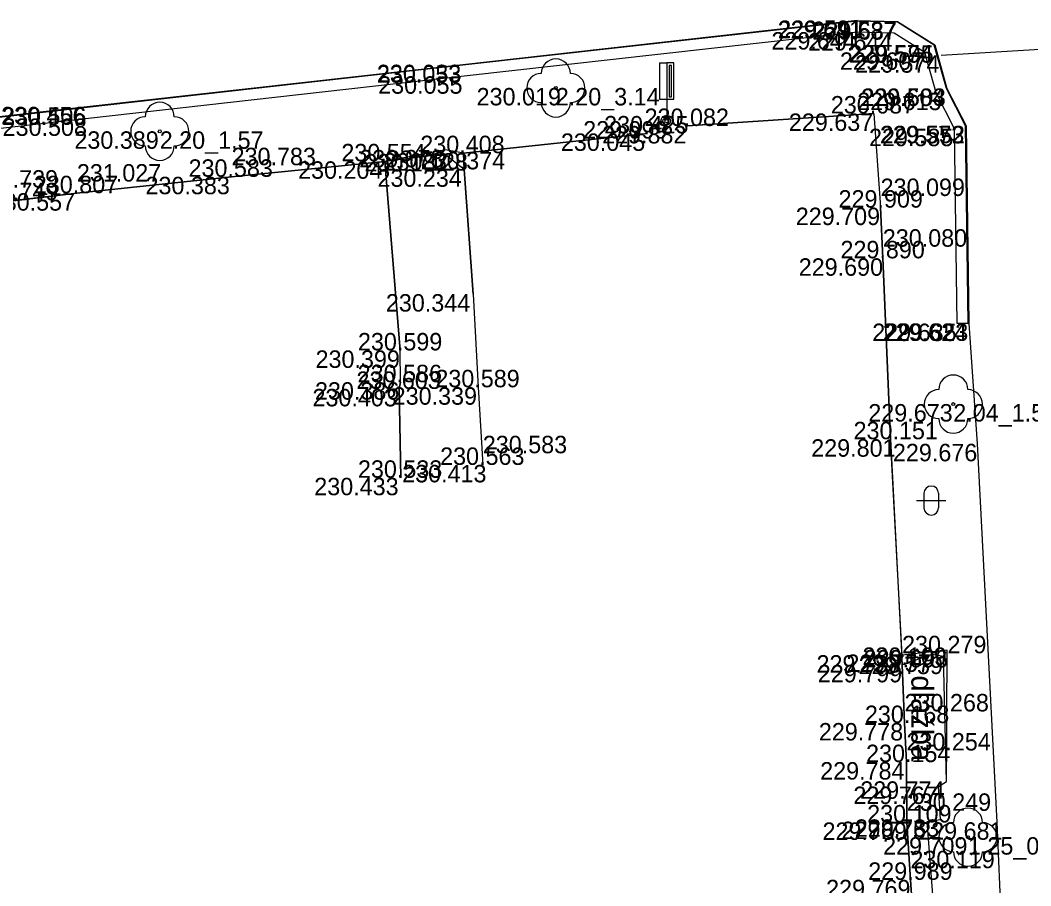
# Model space of a CAD drawing. Extents: x -599516 to -599132, y -1163668 to -1163119.
# Drawn here: x -599435.97 to -599418.59, y -1163529.55 to -1163514.66 of the extents above; entities that cross this region are included whole.
import ezdxf

# ---------------------------------------------------------------- set-up
doc = ezdxf.new("R2010")
doc.units = 0
for name, color, linetype in [('Bod-oznac1', 7, 'Continuous'), ('Bod-oznac2', 7, 'Continuous'), ('Bod-oznac3', 7, 'Continuous'), ('Bod-vyska1', 7, 'Continuous'), ('Bod-vyska2', 7, 'Continuous'), ('Bod-vyska3', 7, 'Continuous'), ('Z_cela-hrobu-dolni-linie', 7, 'Continuous'), ('Z_cela-hrobu-horni-linie', 7, 'Continuous'), ('Z_chodnik', 7, 'Continuous'), ('Z_komunikace', 7, 'Continuous'), ('Z_kultury-znacky', 7, 'Continuous'), ('Z_obvod-kmene-spodek-ve-vysce1_2m', 7, 'Continuous'), ('Z_popis-budov-povrchu', 7, 'Continuous'), ('Z_povrchy-rozhrani-typu', 7, 'Continuous'), ('Z_stromy-kere', 7, 'Continuous'), ('Z_terenni-hrana', 7, 'Continuous'), ('Z_znacky-ostatni-orientacni-sloupek', 7, 'Continuous'), ('Z_zpevnene-plochy', 7, 'Continuous')]:
    doc.layers.add(name, color=color, linetype=linetype)

msp = doc.modelspace()

# ---------------------------------------------------------------- linework, layer by layer
at = {"layer": 'Bod-oznac1'}
for p, q in [((-599421.581, -1163514.662), (-599421.581, -1163514.662)), ((-599421.581, -1163514.672), (-599421.581, -1163514.672)), ((-599420.887, -1163514.692), (-599420.887, -1163514.692)), ((-599420.884, -1163514.682), (-599420.884, -1163514.682)), ((-599421.573, -1163514.862), (-599421.573, -1163514.862)), ((-599420.944, -1163514.88), (-599420.944, -1163514.88)), ((-599420.256, -1163515.089), (-599420.256, -1163515.089)), ((-599420.247, -1163515.083), (-599420.247, -1163515.083)), ((-599420.418, -1163515.211), (-599420.418, -1163515.211)), ((-599420.133, -1163515.26), (-599420.133, -1163515.26)), ((-599428.36, -1163515.423), (-599428.36, -1163515.423)), ((-599428.359, -1163515.433), (-599428.359, -1163515.433)), ((-599428.338, -1163515.622), (-599428.338, -1163515.622)), ((-599426.762, -1163515.823), (-599426.762, -1163515.823)), ((-599420.223, -1163515.904), (-599420.223, -1163515.904)), ((-599420.045, -1163515.835), (-599420.045, -1163515.835)), ((-599420.036, -1163515.831), (-599420.036, -1163515.831)), ((-599434.819, -1163516.148), (-599434.819, -1163516.148)), ((-599434.818, -1163516.158), (-599434.818, -1163516.158)), ((-599421.293, -1163516.262), (-599421.293, -1163516.262)), ((-599434.796, -1163516.347), (-599434.796, -1163516.347)), ((-599424.855, -1163516.393), (-599424.855, -1163516.393)), ((-599424.496, -1163516.477), (-599424.496, -1163516.477)), ((-599419.717, -1163516.476), (-599419.717, -1163516.476)), ((-599419.707, -1163516.474), (-599419.707, -1163516.474)), ((-599433.572, -1163516.569), (-599433.572, -1163516.569)), ((-599425.186, -1163516.605), (-599425.186, -1163516.605)), ((-599419.906, -1163516.524), (-599419.906, -1163516.524)), ((-599428.675, -1163516.959), (-599428.675, -1163516.959)), ((-599428.661, -1163516.888), (-599428.661, -1163516.888)), ((-599428.348, -1163516.944), (-599428.348, -1163516.944)), ((-599429.704, -1163517.085), (-599429.704, -1163517.085)), ((-599432.337, -1163517.351), (-599432.337, -1163517.351)), ((-599428.337, -1163517.223), (-599428.337, -1163517.223)), ((-599434.997, -1163517.633), (-599434.997, -1163517.633)), ((-599421.177, -1163517.881), (-599421.177, -1163517.881)), ((-599421.139, -1163518.753), (-599421.139, -1163518.753)), ((-599428.182, -1163519.369), (-599428.182, -1163519.369)), ((-599419.861, -1163519.876), (-599419.861, -1163519.876)), ((-599419.671, -1163519.873), (-599419.671, -1163519.873)), ((-599419.661, -1163519.873), (-599419.661, -1163519.873)), ((-599429.436, -1163520.337), (-599429.436, -1163520.337)), ((-599429.457, -1163520.999), (-599429.457, -1163520.999)), ((-599429.435, -1163520.884), (-599429.435, -1163520.884)), ((-599428.099, -1163520.971), (-599428.099, -1163520.971)), ((-599419.927, -1163521.26), (-599419.927, -1163521.26)), ((-599421.006, -1163521.865), (-599421.006, -1163521.865)), ((-599419.516, -1163521.944), (-599419.516, -1163521.944)), ((-599428.017, -1163522.306), (-599428.017, -1163522.306)), ((-599429.424, -1163522.528), (-599429.424, -1163522.528)), ((-599420.032, -1163525.49), (-599420.032, -1163525.49)), ((-599420.807, -1163525.579), (-599420.807, -1163525.579)), ((-599420.29, -1163525.567), (-599420.29, -1163525.567)), ((-599420.094, -1163525.604), (-599420.094, -1163525.604)), ((-599420.808, -1163525.746), (-599420.808, -1163525.746)), ((-599420.765, -1163526.746), (-599420.765, -1163526.746)), ((-599420.733, -1163527.418), (-599420.733, -1163527.418)), ((-599420.042, -1163527.749), (-599420.042, -1163527.749)), ((-599420.182, -1163527.839), (-599420.182, -1163527.839)), ((-599420.727, -1163528.456), (-599420.727, -1163528.456)), ((-599420.376, -1163528.442), (-599420.376, -1163528.442)), ((-599420.147, -1163528.403), (-599420.147, -1163528.403)), ((-599419.176, -1163528.453), (-599419.176, -1163528.453)), ((-599419.675, -1163528.709), (-599419.675, -1163528.709)), ((-599420.665, -1163529.443), (-599420.665, -1163529.443))]:
    msp.add_line(p, q, dxfattribs=at)
at = {"layer": 'Bod-oznac2'}
for p, q in [((-599421.293, -1163516.262), (-599421.293, -1163516.262)), ((-599424.496, -1163516.477), (-599424.496, -1163516.477)), ((-599425.186, -1163516.605), (-599425.186, -1163516.605)), ((-599428.348, -1163516.944), (-599428.348, -1163516.944)), ((-599429.704, -1163517.085), (-599429.704, -1163517.085)), ((-599432.337, -1163517.351), (-599432.337, -1163517.351)), ((-599428.337, -1163517.223), (-599428.337, -1163517.223)), ((-599434.997, -1163517.633), (-599434.997, -1163517.633)), ((-599421.177, -1163517.881), (-599421.177, -1163517.881)), ((-599421.139, -1163518.753), (-599421.139, -1163518.753)), ((-599429.436, -1163520.337), (-599429.436, -1163520.337)), ((-599429.457, -1163520.999), (-599429.457, -1163520.999)), ((-599429.435, -1163520.884), (-599429.435, -1163520.884)), ((-599428.099, -1163520.971), (-599428.099, -1163520.971)), ((-599421.006, -1163521.865), (-599421.006, -1163521.865)), ((-599428.017, -1163522.306), (-599428.017, -1163522.306)), ((-599429.424, -1163522.528), (-599429.424, -1163522.528)), ((-599420.808, -1163525.746), (-599420.808, -1163525.746)), ((-599420.765, -1163526.746), (-599420.765, -1163526.746)), ((-599420.733, -1163527.418), (-599420.733, -1163527.418)), ((-599420.727, -1163528.456), (-599420.727, -1163528.456)), ((-599420.665, -1163529.443), (-599420.665, -1163529.443))]:
    msp.add_line(p, q, dxfattribs=at)
at = {"layer": 'Bod-oznac3'}
for p, q in [((-599432.337, -1163517.351), (-599432.337, -1163517.351)), ((-599434.997, -1163517.633), (-599434.997, -1163517.633)), ((-599421.177, -1163517.881), (-599421.177, -1163517.881)), ((-599421.139, -1163518.753), (-599421.139, -1163518.753)), ((-599428.017, -1163522.306), (-599428.017, -1163522.306)), ((-599420.808, -1163525.746), (-599420.808, -1163525.746)), ((-599420.765, -1163526.746), (-599420.765, -1163526.746)), ((-599420.733, -1163527.418), (-599420.733, -1163527.418)), ((-599420.727, -1163528.456), (-599420.727, -1163528.456)), ((-599420.665, -1163529.443), (-599420.665, -1163529.443))]:
    msp.add_line(p, q, dxfattribs=at)
at = {"layer": 'Z_cela-hrobu-dolni-linie'}
msp.add_line((-599421.293, -1163516.262), (-599421.177, -1163517.881), dxfattribs=at)
for points in [[(-599421.293, -1163516.262), (-599424.496, -1163516.477)], [(-599425.186, -1163516.605), (-599428.348, -1163516.944), (-599428.337, -1163517.223)], [(-599429.704, -1163517.085), (-599432.337, -1163517.351), (-599434.997, -1163517.633), (-599436.025, -1163517.754), (-599436.651, -1163517.829), (-599437.614, -1163517.946), (-599438.73, -1163518.122), (-599439.095, -1163518.16), (-599440.238, -1163518.293), (-599441.648, -1163518.432), (-599442.872, -1163518.558), (-599444.321, -1163518.689), (-599445.506, -1163518.817), (-599445.475, -1163519.079), (-599446.807, -1163519.152), (-599446.846, -1163518.718), (-599447.622, -1163518.817), (-599447.636, -1163518.922), (-599449.534, -1163519.065)], [(-599420.439, -1163532.361), (-599420.588, -1163531.085), (-599420.617, -1163530.118), (-599420.665, -1163529.443), (-599420.727, -1163528.456), (-599420.733, -1163527.418), (-599420.765, -1163526.746), (-599420.808, -1163525.746), (-599420.807, -1163525.579), (-599421.006, -1163521.865), (-599421.139, -1163518.753), (-599421.177, -1163517.881)]]:
    msp.add_lwpolyline(points, dxfattribs=at)
at = {"layer": 'Z_cela-hrobu-horni-linie'}
for points in [[(-599424.496, -1163516.477), (-599421.293, -1163516.262), (-599421.177, -1163517.881), (-599421.177, -1163517.881), (-599421.139, -1163518.753), (-599421.139, -1163518.753), (-599421.006, -1163521.865), (-599420.808, -1163525.746), (-599420.808, -1163525.746), (-599420.765, -1163526.746), (-599420.765, -1163526.746), (-599420.733, -1163527.418), (-599420.733, -1163527.418), (-599420.727, -1163528.456), (-599420.727, -1163528.456), (-599420.665, -1163529.443), (-599420.665, -1163529.443), (-599420.617, -1163530.118)], [(-599428.182, -1163519.369), (-599428.337, -1163517.223), (-599428.348, -1163516.944), (-599425.186, -1163516.605)], [(-599437.614, -1163517.946), (-599434.997, -1163517.633), (-599434.997, -1163517.633), (-599432.337, -1163517.351), (-599432.337, -1163517.351), (-599429.704, -1163517.085), (-599429.436, -1163520.337)], [(-599429.435, -1163520.884), (-599429.457, -1163520.999), (-599429.424, -1163522.528)], [(-599428.099, -1163520.971), (-599428.017, -1163522.306), (-599428.017, -1163522.306)]]:
    msp.add_lwpolyline(points, dxfattribs=at)
at = {"layer": 'Z_chodnik'}
for points in [[(-599428.337, -1163517.223), (-599428.675, -1163516.959), (-599429.704, -1163517.085)], [(-599429.424, -1163522.528), (-599429.457, -1163520.999), (-599429.435, -1163520.884), (-599429.436, -1163520.337), (-599429.704, -1163517.085)], [(-599428.337, -1163517.223), (-599428.182, -1163519.369), (-599428.099, -1163520.971), (-599428.017, -1163522.306)]]:
    msp.add_lwpolyline(points, dxfattribs=at)
at = {"layer": 'Z_komunikace'}
msp.add_line((-599421.581, -1163514.662), (-599420.884, -1163514.682), dxfattribs=at)
for points in [[(-599421.581, -1163514.662), (-599428.36, -1163515.423), (-599434.819, -1163516.148), (-599441.683, -1163516.929), (-599449.913, -1163517.876), (-599458.749, -1163518.857), (-599467.027, -1163519.79), (-599473.501, -1163520.532), (-599473.927, -1163520.461), (-599474.378, -1163520.597), (-599474.641, -1163520.812), (-599479.573, -1163521.271)], [(-599420.884, -1163514.682), (-599420.247, -1163515.083), (-599420.036, -1163515.831), (-599419.707, -1163516.474), (-599419.661, -1163519.873), (-599419.516, -1163521.944), (-599419.176, -1163528.453), (-599418.955, -1163533.678), (-599418.894, -1163534.146)]]:
    msp.add_lwpolyline(points, dxfattribs=at)
at = {"layer": 'Z_kultury-znacky'}
for p, q in [((-599420.432, -1163522.795), (-599420.432, -1163523.045)), ((-599420.182, -1163522.795), (-599420.182, -1163523.045)), ((-599420.557, -1163522.92), (-599420.057, -1163522.92))]:
    msp.add_line(p, q, dxfattribs=at)
for centre, start, end in [((-599420.307, -1163522.795), 0, 180), ((-599420.307, -1163523.045), 180, 0)]:
    msp.add_arc(centre, 0.125, start, end, dxfattribs=at)
at = {"layer": 'Z_povrchy-rozhrani-typu'}
msp.add_lwpolyline([(-599420.133, -1163515.26), (-599415.884, -1163514.999)], dxfattribs=at)
at = {"layer": 'Z_stromy-kere'}
for centre in [(-599426.762, -1163515.823), (-599433.572, -1163516.569), (-599419.927, -1163521.26), (-599419.675, -1163528.709)]:
    msp.add_circle(centre, 0.025, dxfattribs=at)
for centre, start, end in [((-599426.762, -1163515.573), 0, 180), ((-599427.012, -1163515.823), 90, 270), ((-599426.512, -1163515.823), 270, 90), ((-599433.572, -1163516.319), 0, 180), ((-599426.762, -1163516.073), 180, 0), ((-599433.822, -1163516.569), 90, 270), ((-599433.322, -1163516.569), 270, 90), ((-599433.572, -1163516.819), 180, 0), ((-599419.927, -1163521.01), 0, 180), ((-599420.177, -1163521.26), 90, 270), ((-599419.677, -1163521.26), 270, 90), ((-599419.927, -1163521.51), 180, 0), ((-599419.675, -1163528.459), 0, 180), ((-599419.925, -1163528.709), 90, 270), ((-599419.425, -1163528.709), 270, 90), ((-599419.675, -1163528.959), 180, 0)]:
    msp.add_arc(centre, 0.25, start, end, dxfattribs=at)
at = {"layer": 'Z_terenni-hrana'}
for points in [[(-599428.348, -1163516.944), (-599428.661, -1163516.888), (-599429.704, -1163517.085)], [(-599420.042, -1163527.749), (-599420.032, -1163525.49), (-599420.807, -1163525.579)]]:
    msp.add_lwpolyline(points, dxfattribs=at)
at = {"layer": 'Z_znacky-ostatni-orientacni-sloupek'}
for p, q in [((-599424.98, -1163515.393), (-599424.98, -1163516.018)), ((-599424.98, -1163515.393), (-599424.855, -1163515.393)), ((-599424.98, -1163516.018), (-599424.855, -1163516.018)), ((-599424.855, -1163516.018), (-599424.855, -1163516.293))]:
    msp.add_line(p, q, dxfattribs=at)
for points in [[(-599424.855, -1163516.018), (-599424.73, -1163516.018), (-599424.73, -1163515.393), (-599424.855, -1163515.393)], [(-599424.812, -1163515.975), (-599424.772, -1163515.975), (-599424.772, -1163515.436), (-599424.812, -1163515.436)]]:
    msp.add_lwpolyline(points, close=True, dxfattribs=at)
for radius in [0.1, 0.065, 0.03]:
    msp.add_circle((-599424.855, -1163516.393), radius, dxfattribs=at)
at = {"layer": 'Z_zpevnene-plochy'}
for points in [[(-599419.671, -1163519.873), (-599419.717, -1163516.476), (-599420.045, -1163515.835), (-599420.256, -1163515.089), (-599420.887, -1163514.692), (-599421.581, -1163514.672), (-599428.359, -1163515.433), (-599434.818, -1163516.158), (-599441.682, -1163516.939), (-599449.912, -1163517.886), (-599458.748, -1163518.867), (-599467.026, -1163519.8), (-599473.501, -1163520.542), (-599473.926, -1163520.471), (-599474.373, -1163520.606), (-599474.637, -1163520.822), (-599479.572, -1163521.281), (-599480.282, -1163521.415), (-599480.802, -1163521.956), (-599481.292, -1163522.751)], [(-599419.671, -1163519.873), (-599419.861, -1163519.876), (-599419.906, -1163516.524), (-599420.223, -1163515.904), (-599420.418, -1163515.211), (-599420.944, -1163514.88), (-599421.573, -1163514.862), (-599428.338, -1163515.622), (-599434.796, -1163516.347), (-599441.66, -1163517.128), (-599449.89, -1163518.075), (-599458.727, -1163519.056), (-599467.004, -1163519.989), (-599473.506, -1163520.734), (-599473.914, -1163520.666), (-599474.282, -1163520.777), (-599474.562, -1163521.005), (-599479.545, -1163521.469), (-599480.187, -1163521.591), (-599480.651, -1163522.073), (-599481.13, -1163522.851), (-599481.292, -1163522.751)], [(-599420.588, -1163531.085), (-599420.178, -1163531.034), (-599420.376, -1163528.442), (-599420.147, -1163528.403), (-599420.182, -1163527.839), (-599420.042, -1163527.749), (-599420.094, -1163525.604), (-599420.29, -1163525.567), (-599420.808, -1163525.746)]]:
    msp.add_lwpolyline(points, dxfattribs=at)

# ---------------------------------------------------------------- texts
at = {"layer": 'Bod-vyska1'}
for s, p in [('229.641', (-599422.947, -1163514.972)), ('229.591', (-599422.936, -1163514.962)), ('229.587', (-599422.356, -1163514.982)), ('229.637', (-599422.348, -1163514.992)), ('229.644', (-599423.054, -1163515.162)), ('229.644', (-599422.425, -1163515.18)), ('229.574', (-599421.73, -1163515.383)), ('229.595', (-599421.715, -1163515.389)), ('229.607', (-599421.877, -1163515.511)), ('229.574', (-599421.616, -1163515.56)), ('230.033', (-599429.838, -1163515.723)), ('230.053', (-599429.837, -1163515.733)), ('230.055', (-599429.816, -1163515.922)), ('230.019', (-599428.124, -1163516.123)), ('229.615', (-599421.578, -1163516.204)), ('229.604', (-599421.513, -1163516.135)), ('229.583', (-599421.506, -1163516.131)), ('230.456', (-599436.299, -1163516.448)), ('230.506', (-599436.284, -1163516.458)), ('229.637', (-599422.754, -1163516.562)), ('230.508', (-599436.274, -1163516.647)), ('229.999', (-599426.291, -1163516.693)), ('229.882', (-599425.966, -1163516.777)), ('229.573', (-599421.189, -1163516.776)), ('229.552', (-599421.177, -1163516.774)), ('230.389', (-599435.04, -1163516.869)), ('230.045', (-599426.675, -1163516.905)), ('229.585', (-599421.376, -1163516.824)), ('230.078', (-599430.141, -1163517.188)), ('230.187', (-599430.053, -1163517.259)), ('230.128', (-599429.724, -1163517.244)), ('230.204', (-599431.193, -1163517.385)), ('230.383', (-599433.817, -1163517.651)), ('230.234', (-599429.828, -1163517.523)), ('230.557', (-599436.478, -1163517.933)), ('229.709', (-599422.636, -1163518.181)), ('229.690', (-599422.585, -1163519.053)), ('230.344', (-599429.684, -1163519.669)), ('229.635', (-599421.32, -1163520.176)), ('229.624', (-599421.141, -1163520.173)), ('229.623', (-599421.12, -1163520.173)), ('230.399', (-599430.893, -1163520.637)), ('230.403', (-599430.946, -1163521.299)), ('230.386', (-599430.903, -1163521.184)), ('230.339', (-599429.567, -1163521.271)), ('229.673', (-599421.388, -1163521.56)), ('229.801', (-599422.37, -1163522.165)), ('229.676', (-599420.965, -1163522.244)), ('230.413', (-599429.404, -1163522.606)), ('230.433', (-599430.915, -1163522.828)), ('229.696', (-599421.468, -1163525.79)), ('229.738', (-599422.279, -1163525.879)), ('229.757', (-599421.764, -1163525.867)), ('229.759', (-599421.555, -1163525.904)), ('229.799', (-599422.257, -1163526.046)), ('229.778', (-599422.239, -1163527.046)), ('229.784', (-599422.216, -1163527.718)), ('229.774', (-599421.527, -1163528.049)), ('229.767', (-599421.645, -1163528.139)), ('229.769', (-599422.176, -1163528.756)), ('229.775', (-599421.85, -1163528.742)), ('229.783', (-599421.619, -1163528.703)), ('229.681', (-599420.531, -1163528.753)), ('229.709', (-599421.134, -1163529.009)), ('229.769', (-599422.114, -1163529.743))]:
    msp.add_text(s, height=0.3, dxfattribs=at).set_placement(p)
at = {"layer": 'Bod-vyska2'}
for s, p in [('230.087', (-599422.033, -1163516.262)), ('230.425', (-599425.931, -1163516.605)), ('230.082', (-599425.235, -1163516.477)), ('230.408', (-599429.092, -1163516.944)), ('230.554', (-599430.449, -1163517.085)), ('230.374', (-599429.083, -1163517.223)), ('230.583', (-599433.077, -1163517.351)), ('230.739', (-599436.77, -1163517.537)), ('230.807', (-599435.737, -1163517.633)), ('230.749', (-599436.766, -1163517.754)), ('229.909', (-599421.9, -1163517.881)), ('229.890', (-599421.867, -1163518.753)), ('230.599', (-599430.164, -1163520.337)), ('230.586', (-599430.169, -1163520.884)), ('230.603', (-599430.19, -1163520.999)), ('230.589', (-599428.833, -1163520.971)), ('230.151', (-599421.642, -1163521.865)), ('230.563', (-599428.751, -1163522.306)), ('230.533', (-599430.164, -1163522.528)), ('230.109', (-599421.489, -1163525.746)), ('230.168', (-599421.447, -1163526.746)), ('230.154', (-599421.427, -1163527.418)), ('230.109', (-599421.408, -1163528.456)), ('229.989', (-599421.389, -1163529.443))]:
    msp.add_text(s, height=0.3, dxfattribs=at).set_placement(p)
at = {"layer": 'Bod-vyska3'}
for s, p in [('230.783', (-599432.337, -1163517.151)), ('231.027', (-599434.997, -1163517.433)), ('230.099', (-599421.177, -1163517.681)), ('230.080', (-599421.139, -1163518.553)), ('230.583', (-599428.017, -1163522.106)), ('230.279', (-599420.808, -1163525.546)), ('230.268', (-599420.765, -1163526.546)), ('230.254', (-599420.733, -1163527.218)), ('230.249', (-599420.727, -1163528.256)), ('230.119', (-599420.665, -1163529.243))]:
    msp.add_text(s, height=0.3, dxfattribs=at).set_placement(p)
at = {"layer": 'Z_obvod-kmene-spodek-ve-vysce1_2m'}
for s, p in [('2.20_3.14', (-599426.762, -1163516.123)), ('2.20_1.57', (-599433.572, -1163516.869)), ('2.04_1.56', (-599419.927, -1163521.56)), ('1.25_0.94', (-599419.675, -1163529.009))]:
    msp.add_text(s, height=0.3, dxfattribs=at).set_placement(p)
at = {"layer": 'Z_popis-budov-povrchu'}
msp.add_text('dlažba', height=0.375, rotation=270, dxfattribs=at).set_placement((-599420.648, -1163525.926))

doc.saveas('drawing.dxf')
